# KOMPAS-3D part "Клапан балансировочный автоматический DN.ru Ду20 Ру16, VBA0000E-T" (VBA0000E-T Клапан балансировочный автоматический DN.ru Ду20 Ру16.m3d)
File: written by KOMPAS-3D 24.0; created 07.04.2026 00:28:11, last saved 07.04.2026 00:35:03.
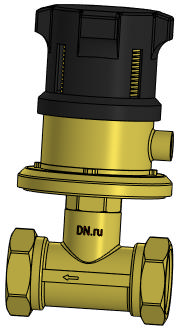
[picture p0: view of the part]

Document properties: Автор: tyuri; Полное имя файла: D:\Аутсорс\VBA0000E-T Клапан балансировочный автоматический DN.ru\DN20\VBA0000E-T Клапан балансировочный автоматический DN.ru Ду20 Ру16.m3d

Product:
- Body: Тело 5  | qty 1
    Масса: 1.11353
- Part/product: Клапан балансировочный автоматический DN.ru Ду20 Ру16  | designation VBA0000E-T
    Масса: 0.706
    Раздел спецификации: Прочие изделия
    Примечание: D080-01201

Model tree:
1. Операция без истории:1

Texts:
  VBA0000E-T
